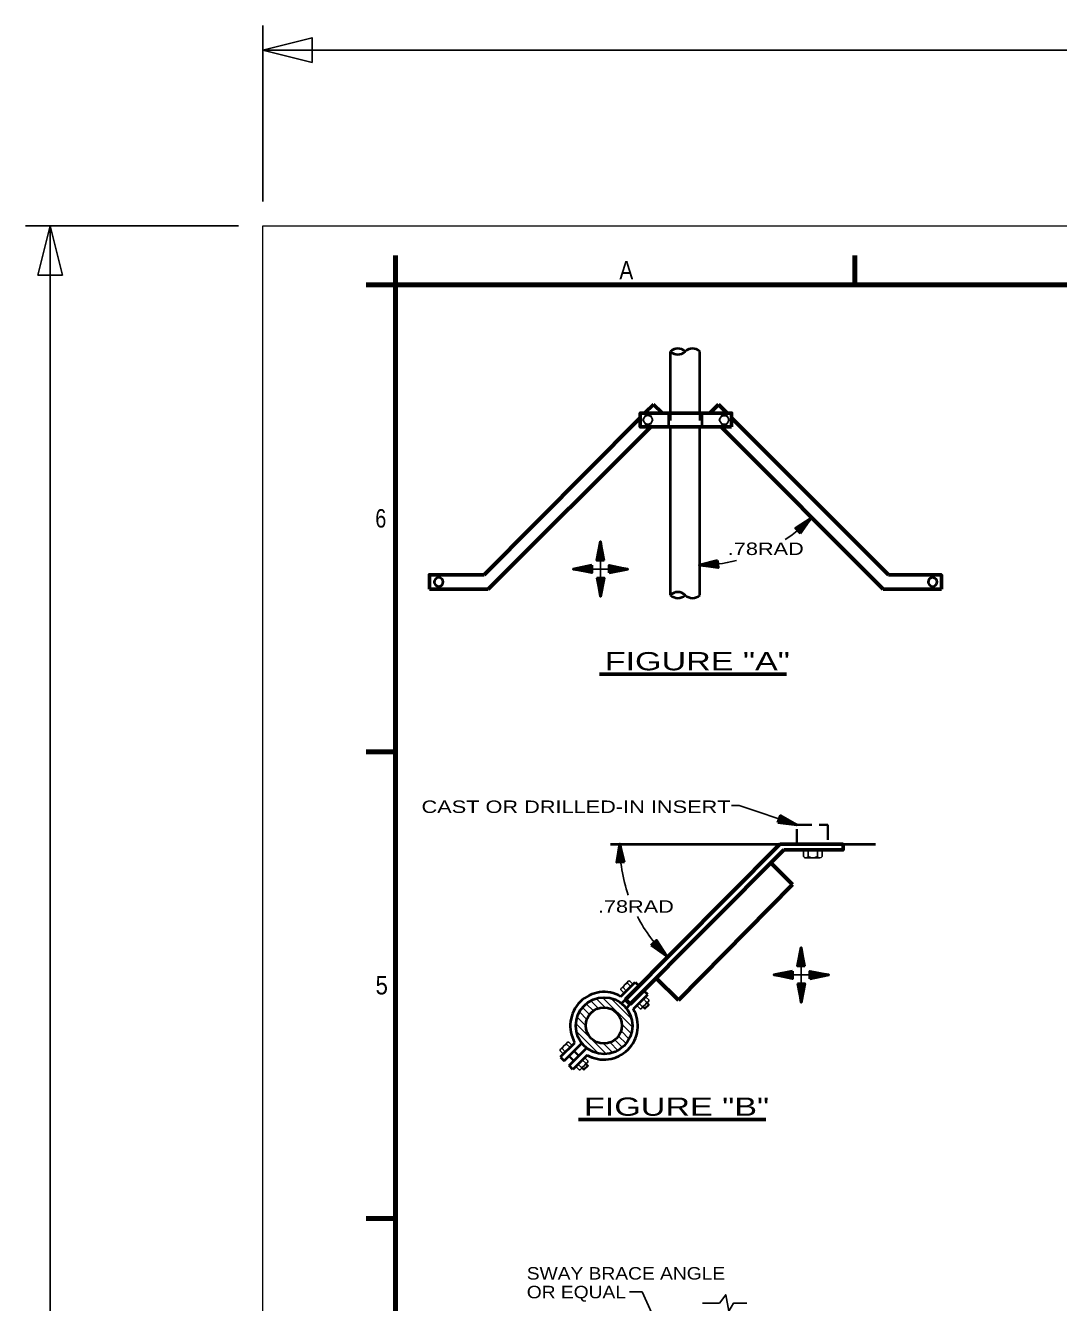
# Model space of a CAD drawing. Extents: x 55 to 190, y 198 to 264.
# Drawn here: x 57.66 to 78.68, y 235.95 to 261.93 of the extents above; entities that cross this region are included whole.
import ezdxf
from ezdxf.enums import TextEntityAlignment as Align

# ---------------------------------------------------------------- set-up
doc = ezdxf.new("R2010")
doc.units = 0
doc.header["$LTSCALE"] = 0.1
doc.linetypes.add('MEDIUM_DASHED', pattern=[4.5, 3, -1.5])
doc.linetypes.add('SHORT_DASHED', pattern=[2.7, 1.5, -1.2])
for name, color, linetype, lineweight in [('1', 7, 'Continuous', 25), ('2', 7, 'Continuous', 40), ('3', 7, 'Continuous', 25)]:
    doc.layers.add(name, color=color, linetype=linetype, lineweight=lineweight)

msp = doc.modelspace()

# ---------------------------------------------------------------- linework, layer by layer
at = {"layer": '1', "lineweight": 80}
for p, q in [((74.5415, 257.2525), (74.5415, 256.6525)), ((65.1915, 247.1525), (64.5915, 247.1525)), ((65.1915, 237.6525), (64.5915, 237.6525))]:
    msp.add_line(p, q, dxfattribs=at)
at = {"layer": '1', "lineweight": 13}
msp.add_lwpolyline([(62.4915, 257.8525), (146.5927, 257.8525), (146.5927, 198.4512), (62.4915, 198.4512)], close=True, dxfattribs=at)
at = {"layer": '1', "lineweight": 80}
msp.add_lwpolyline([(65.1915, 257.2525), (65.1915, 256.6525), (64.5915, 256.6525)], dxfattribs=at)
msp.add_lwpolyline([(65.1915, 256.6525), (145.3927, 256.6525), (145.3927, 199.6512), (65.1915, 199.6512)], close=True, dxfattribs=at)
at = {"layer": '2'}
for p, q in [((70.7891, 254.0452), (70.7891, 255.2974)), ((71.3844, 254.0452), (71.3844, 255.2974)), ((70.7476, 254.0459), (70.7476, 253.7642)), ((71.4265, 254.0483), (71.4265, 253.7626)), ((70.7891, 250.3421), (70.7891, 253.7644)), ((71.3844, 250.3421), (71.3844, 253.7644)), ((73.6593, 251.9108), (73.3442, 251.6869)), ((73.6593, 251.9108), (73.3701, 251.66)), ((73.3831, 251.6459), (73.6593, 251.9108)), ((73.6593, 251.9108), (73.3958, 251.6332)), ((73.6593, 251.9108), (73.4069, 251.6205)), ((73.6593, 251.9108), (73.4222, 251.6054)), ((69.3611, 251.4303), (69.305, 251.048)), ((69.3611, 251.4303), (69.3424, 251.048)), ((69.3617, 251.0477), (69.3611, 251.4303)), ((69.3611, 251.4303), (69.3966, 251.0474)), ((69.3611, 251.4303), (69.3794, 251.048)), ((69.3611, 251.4303), (69.418, 251.048)), ((71.3683, 250.9514), (71.7472, 251.0281)), ((68.8026, 250.8715), (69.1849, 250.9284)), ((68.8026, 250.8715), (69.1855, 250.9069)), ((68.8026, 250.8715), (69.1849, 250.8897)), ((69.1852, 250.872), (68.8026, 250.8715)), ((68.8026, 250.8715), (69.1849, 250.8154)), ((68.8026, 250.8715), (69.1849, 250.8527)), ((69.9199, 250.8715), (69.5371, 250.836)), ((69.5374, 250.871), (69.9199, 250.8715)), ((69.9199, 250.8715), (69.5376, 250.9276)), ((69.9199, 250.8715), (69.5376, 250.8903)), ((69.9199, 250.8715), (69.5376, 250.8532)), ((69.9199, 250.8715), (69.5376, 250.8146)), ((71.3683, 250.9514), (71.7487, 251.007)), ((71.3683, 250.9514), (71.7493, 250.99)), ((71.7503, 250.972), (71.3683, 250.9514)), ((71.3683, 250.9514), (71.7511, 250.953)), ((71.3683, 250.9514), (71.753, 250.9157)), ((69.3611, 250.313), (69.3043, 250.6953)), ((69.3611, 250.313), (69.3257, 250.6958)), ((69.3611, 250.313), (69.3429, 250.6953)), ((69.3606, 250.6955), (69.3611, 250.313)), ((69.3611, 250.313), (69.4172, 250.6953)), ((69.3611, 250.313), (69.3799, 250.6953)), ((73.3608, 245.6642), (73.0161, 245.8389)), ((73.3608, 245.6642), (72.9804, 245.732)), ((73.3608, 245.6642), (72.9865, 245.7526)), ((73.3608, 245.6642), (72.9925, 245.7685)), ((72.9978, 245.7854), (73.3608, 245.6642)), ((73.3608, 245.6642), (73.0042, 245.8036)), ((69.5635, 245.2753), (74.9581, 245.2753)), ((69.7532, 245.2822), (69.7175, 244.8975)), ((69.7739, 244.9001), (69.7532, 245.2822)), ((69.7532, 245.2822), (69.8088, 244.9017)), ((69.7532, 245.2822), (69.7548, 244.8993)), ((69.7532, 245.2822), (69.7919, 244.9012)), ((69.7532, 245.2822), (69.83, 244.9033)), ((70.7126, 242.9911), (70.4073, 243.2282)), ((70.7126, 242.9911), (70.4224, 243.2436)), ((70.7126, 242.9911), (70.4351, 243.2547)), ((70.4478, 243.2674), (70.7126, 242.9911)), ((70.7126, 242.9911), (70.4618, 243.2803)), ((70.7126, 242.9911), (70.4888, 243.3063)), ((73.4474, 243.1705), (73.3913, 242.7882)), ((73.4474, 243.1705), (73.4286, 242.7882)), ((73.4479, 242.7879), (73.4474, 243.1705)), ((73.4474, 243.1705), (73.4828, 242.7877)), ((73.4474, 243.1705), (73.4656, 242.7882)), ((73.4474, 243.1705), (73.5042, 242.7882)), ((69.7787, 242.1733), (70.0705, 242.4651)), ((70.0705, 242.4651), (70.1464, 242.3892)), ((72.8888, 242.6117), (73.2712, 242.6686)), ((72.8888, 242.6117), (73.2717, 242.6472)), ((72.8888, 242.6117), (73.2712, 242.63)), ((73.2714, 242.6123), (72.8888, 242.6117)), ((72.8888, 242.6117), (73.2712, 242.5556)), ((72.8888, 242.6117), (73.2712, 242.5929)), ((73.4474, 242.0532), (73.3905, 242.4355)), ((73.4474, 242.0532), (73.4119, 242.436)), ((73.4474, 242.0532), (73.4291, 242.4355)), ((73.4468, 242.4358), (73.4474, 242.0532)), ((73.4474, 242.0532), (73.5035, 242.4355)), ((73.4474, 242.0532), (73.4662, 242.4355)), ((74.0062, 242.6117), (73.6233, 242.5763)), ((73.6236, 242.6112), (74.0062, 242.6117)), ((74.0062, 242.6117), (73.6238, 242.6678)), ((74.0062, 242.6117), (73.6238, 242.6305)), ((74.0062, 242.6117), (73.6238, 242.5935)), ((74.0062, 242.6117), (73.6238, 242.5548)), ((70.0305, 241.9214), (70.3224, 242.2133)), ((70.3224, 242.2133), (70.2446, 242.2913)), ((69.7914, 242.0325), (69.8705, 242.1122)), ((69.889, 241.9355), (69.9686, 242.0156)), ((68.5494, 240.943), (68.8394, 241.233)), ((68.6248, 240.8639), (68.9809, 241.22)), ((68.547, 240.9417), (68.6248, 240.8639)), ((68.7211, 240.7678), (69.0772, 241.1237)), ((69.0907, 240.9819), (68.7989, 240.6901)), ((68.7989, 240.6901), (68.7211, 240.7678))]:
    msp.add_line(p, q, dxfattribs=at)
at = {"layer": '2', "lineweight": 60}
for p, q in [((70.442, 254.2227), (70.2665, 254.0473)), ((70.442, 254.2227), (70.6176, 254.0473)), ((71.5974, 254.0483), (71.7657, 254.2166)), ((71.9337, 254.0483), (71.7657, 254.2166)), ((66.9965, 250.7559), (70.1694, 253.9512)), ((70.2658, 254.0462), (70.2665, 254.0473)), ((71.9355, 254.0465), (71.9347, 254.0473)), ((75.2264, 250.7527), (72.0311, 253.9512)), ((70.3867, 253.7631), (67.0775, 250.4593)), ((75.1158, 250.4593), (71.8154, 253.7626)), ((67.0775, 250.4593), (65.879, 250.4593)), ((75.1158, 250.4593), (76.2996, 250.4593)), ((69.3389, 248.7339), (73.1471, 248.7339)), ((69.8705, 242.1122), (73.0153, 245.2716)), ((69.9686, 242.0156), (73.0949, 245.1568)), ((73.0153, 245.2716), (74.2988, 245.2753)), ((73.2717, 244.4495), (72.8293, 244.8898)), ((70.9478, 242.0992), (73.2717, 244.4495)), ((70.9478, 242.0992), (70.4978, 242.5472)), ((69.8705, 242.1122), (69.9686, 242.0156)), ((68.9164, 239.6693), (72.7245, 239.6693))]:
    msp.add_line(p, q, dxfattribs=at)
at = {"layer": '2', "linetype": 'SHORT_DASHED', "lineweight": 35}
for p, q in [((70.7891, 254.0452), (70.7891, 253.7626)), ((71.3844, 254.0452), (71.3844, 253.7626))]:
    msp.add_line(p, q, dxfattribs=at)
at = {"layer": '2', "lineweight": 25}
for p, q in [((69.3611, 250.313), (69.3611, 251.4303)), ((68.8026, 250.8715), (69.9199, 250.8715)), ((73.8723, 245.1565), (73.4931, 245.1565)), ((73.4934, 245.0242), (73.4931, 245.1565)), ((73.5876, 245.0242), (73.5876, 245.1568)), ((73.7786, 245.0245), (73.7786, 245.1565)), ((73.8718, 245.0242), (73.8723, 245.1565)), ((73.8247, 244.9959), (73.5408, 244.9959)), ((73.4474, 242.0532), (73.4474, 243.1705)), ((69.7871, 242.3453), (69.921, 242.4792)), ((69.912, 242.4437), (69.9744, 242.3813)), ((69.9564, 242.4882), (70.0189, 242.426)), ((72.8888, 242.6117), (74.0062, 242.6117)), ((69.7781, 242.3098), (69.8403, 242.2474)), ((69.8223, 242.3538), (69.8845, 242.2916)), ((69.8403, 242.2474), (70.0189, 242.426)), ((70.1054, 241.986), (70.2814, 242.1672)), ((70.1689, 241.9249), (70.1054, 241.986)), ((70.212, 241.9696), (70.1491, 242.031)), ((70.2041, 241.9344), (70.3361, 242.0701)), ((70.3007, 242.0606), (70.2374, 242.1223)), ((70.3446, 242.1058), (70.2814, 242.1672)), ((68.5478, 241.1031), (68.6817, 241.237)), ((68.601, 241.0052), (68.7796, 241.1838)), ((68.6727, 241.2015), (68.7351, 241.139)), ((68.7171, 241.246), (68.7796, 241.1838)), ((68.5388, 241.0676), (68.601, 241.0052)), ((68.583, 241.1115), (68.6452, 241.0494)), ((68.8661, 240.7438), (69.0421, 240.925)), ((69.0614, 240.8184), (68.9981, 240.88)), ((69.1053, 240.8636), (69.0421, 240.925)), ((68.9296, 240.6827), (68.8661, 240.7438)), ((68.9727, 240.7274), (68.9098, 240.7887)), ((68.9648, 240.6922), (69.0968, 240.8279))]:
    msp.add_line(p, q, dxfattribs=at)
at = {"layer": '2', "lineweight": 13}
for p, q in [((69.1392, 241.8061), (68.995, 241.9503)), ((69.2175, 241.8812), (69.0725, 242.0262)), ((69.3196, 241.932), (69.1646, 242.0871)), ((69.4572, 241.9479), (69.2733, 242.1315)), ((70.0123, 241.5463), (69.4045, 242.154)), ((69.9964, 241.7156), (69.5731, 242.1384)), ((69.0627, 241.5759), (68.8859, 241.7529)), ((69.0847, 241.7074), (68.9322, 241.8598)), ((69.4828, 241.0025), (68.8608, 241.6246)), ((69.3199, 241.0123), (68.8706, 241.4616)), ((69.9453, 241.3065), (69.7805, 241.4711)), ((69.9898, 241.4147), (69.7964, 241.6087)), ((69.6112, 241.0277), (69.4246, 241.2142)), ((69.7181, 241.074), (69.5556, 241.2362)), ((69.8085, 241.1367), (69.6546, 241.2907)), ((69.8842, 241.2142), (69.7297, 241.369))]:
    msp.add_line(p, q, dxfattribs=at)
at = {"layer": '2', "lineweight": 35}
for p, q in [((68.7214, 240.9605), (68.8177, 240.8644)), ((68.823, 241.0621), (68.9193, 240.966))]:
    msp.add_line(p, q, dxfattribs=at)
at = {"layer": '2', "lineweight": 60}
msp.add_lwpolyline([(72.0292, 253.7629), (70.1705, 253.7629), (70.1705, 254.0459), (72.0292, 254.0459)], close=True, dxfattribs=at)
at = {"layer": '2', "lineweight": 25}
for points in [[(70.4293, 253.9081), (70.3779, 253.819), (70.2755, 253.819), (70.2247, 253.9081), (70.2755, 253.9957), (70.3779, 253.9957)], [(71.9821, 253.9055), (71.9308, 253.8163), (71.8284, 253.8163), (71.7776, 253.9055), (71.8284, 253.993), (71.9308, 253.993)]]:
    msp.add_lwpolyline(points, close=True, dxfattribs=at)
for points in [[(70.4144, 253.9081), (70.4144, 253.902), (70.4134, 253.8965), (70.4126, 253.8909), (70.4118, 253.8854), (70.4099, 253.8801), (70.4084, 253.8748), (70.4062, 253.8703), (70.4033, 253.8645), (70.4007, 253.86), (70.3978, 253.8557), (70.3943, 253.8512), (70.3906, 253.8473), (70.3864, 253.8436), (70.3827, 253.8396), (70.3779, 253.8361), (70.3737, 253.833), (70.3692, 253.8306), (70.3639, 253.8279), (70.3591, 253.8253), (70.3536, 253.8242), (70.3486, 253.8219), (70.343, 253.8213), (70.3377, 253.8205), (70.3319, 253.82), (70.3271, 253.82), (70.3213, 253.82), (70.3155, 253.8205), (70.3099, 253.8213), (70.3046, 253.8219), (70.2996, 253.8242), (70.2938, 253.8253), (70.2893, 253.8279), (70.2843, 253.8306), (70.2792, 253.833), (70.2753, 253.8361), (70.2705, 253.8396), (70.2668, 253.8436), (70.2628, 253.8473), (70.2586, 253.8512), (70.2552, 253.8557), (70.2528, 253.86), (70.2499, 253.8645), (70.247, 253.8703), (70.2448, 253.8748), (70.2433, 253.8801), (70.2414, 253.8854), (70.2406, 253.8909), (70.2401, 253.8965), (70.239, 253.902), (70.239, 253.9081), (70.239, 253.9129), (70.2401, 253.9182), (70.2406, 253.9237), (70.2414, 253.9295), (70.2433, 253.9346), (70.2448, 253.9399), (70.247, 253.9443), (70.2499, 253.9497), (70.2528, 253.9547), (70.2552, 253.9589), (70.2586, 253.9637), (70.2628, 253.9674), (70.2668, 253.9713), (70.2705, 253.9751), (70.2753, 253.9785), (70.2792, 253.9817), (70.2843, 253.9843), (70.2893, 253.9867), (70.2938, 253.9893), (70.2996, 253.9907), (70.3046, 253.9923), (70.3099, 253.9936), (70.3155, 253.9944), (70.3213, 253.9949), (70.3271, 253.9949), (70.3319, 253.9949), (70.3377, 253.9944), (70.343, 253.9936), (70.3486, 253.9923), (70.3536, 253.9907), (70.3591, 253.9893), (70.3639, 253.9867), (70.3692, 253.9843), (70.3737, 253.9817), (70.3779, 253.9785), (70.3827, 253.9751), (70.3864, 253.9713), (70.3906, 253.9674), (70.3943, 253.9637), (70.3978, 253.9589), (70.4007, 253.9547), (70.4033, 253.9497), (70.4062, 253.9443), (70.4084, 253.9399), (70.4099, 253.9346), (70.4118, 253.9295), (70.4126, 253.9237), (70.4134, 253.9182)], [(71.9673, 253.9055), (71.9673, 253.8994), (71.9662, 253.8938), (71.9654, 253.8883), (71.9646, 253.8827), (71.9628, 253.8774), (71.9612, 253.8721), (71.9591, 253.8676), (71.9562, 253.8618), (71.9535, 253.8573), (71.9506, 253.8531), (71.9472, 253.8486), (71.9435, 253.8446), (71.9392, 253.8409), (71.9355, 253.8369), (71.9308, 253.8335), (71.9265, 253.8303), (71.922, 253.8279), (71.9168, 253.8253), (71.912, 253.8227), (71.9064, 253.8216), (71.9014, 253.8192), (71.8958, 253.8187), (71.8906, 253.8179), (71.8847, 253.8174), (71.88, 253.8174), (71.8742, 253.8174), (71.8683, 253.8179), (71.8628, 253.8187), (71.8575, 253.8192), (71.8525, 253.8216), (71.8466, 253.8227), (71.8421, 253.8253), (71.8371, 253.8279), (71.8321, 253.8303), (71.8281, 253.8335), (71.8234, 253.8369), (71.8196, 253.8409), (71.8157, 253.8446), (71.8114, 253.8486), (71.808, 253.8531), (71.8056, 253.8573), (71.8027, 253.8618), (71.7998, 253.8676), (71.7977, 253.8721), (71.7961, 253.8774), (71.7942, 253.8827), (71.7935, 253.8883), (71.7929, 253.8938), (71.7919, 253.8994), (71.7919, 253.9055), (71.7919, 253.9102), (71.7929, 253.9155), (71.7935, 253.9211), (71.7942, 253.9269), (71.7961, 253.9319), (71.7977, 253.9372), (71.7998, 253.9417), (71.8027, 253.947), (71.8056, 253.952), (71.808, 253.9563), (71.8114, 253.961), (71.8157, 253.9647), (71.8196, 253.9687), (71.8234, 253.9724), (71.8281, 253.9758), (71.8321, 253.979), (71.8371, 253.9817), (71.8421, 253.9841), (71.8466, 253.9867), (71.8525, 253.988), (71.8575, 253.9896), (71.8628, 253.9909), (71.8683, 253.9917), (71.8742, 253.9923), (71.88, 253.9923), (71.8847, 253.9923), (71.8906, 253.9917), (71.8958, 253.9909), (71.9014, 253.9896), (71.9064, 253.988), (71.912, 253.9867), (71.9168, 253.9841), (71.922, 253.9817), (71.9265, 253.979), (71.9308, 253.9758), (71.9355, 253.9724), (71.9392, 253.9687), (71.9435, 253.9647), (71.9472, 253.961), (71.9506, 253.9563), (71.9535, 253.952), (71.9562, 253.947), (71.9591, 253.9417), (71.9612, 253.9372), (71.9628, 253.9319), (71.9646, 253.9269), (71.9654, 253.9211), (71.9662, 253.9155)], [(72.0266, 246.0579), (72.1877, 246.0579), (73.3608, 245.6642)], [(69.952, 236.1636), (70.2089, 236.1636), (70.8507, 234.7515)], [(71.4389, 235.9305), (71.7813, 235.9305), (71.9128, 236.1025), (71.9765, 235.768), (72.0657, 235.9323), (72.3403, 235.9323)]]:
    msp.add_lwpolyline(points, dxfattribs=at)
at = {"layer": '2'}
for points in [[(73.4357, 251.5914), (73.3301, 251.7023), (73.6593, 251.9108)], [(73.4357, 251.5914), (73.6593, 251.9108), (73.3569, 251.6734)], [(69.4373, 251.048), (69.2844, 251.0482), (69.3611, 251.4303)], [(69.4373, 251.048), (69.3611, 251.4303), (69.3236, 251.0477)], [(71.7461, 251.0477), (71.754, 250.8948), (71.3683, 250.9514)], [(71.7461, 251.0477), (71.3683, 250.9514), (71.7524, 250.9339)], [(69.1849, 250.9477), (69.1847, 250.7948), (68.8026, 250.8715)], [(69.1849, 250.9477), (68.8026, 250.8715), (69.1852, 250.8339)], [(69.5376, 250.7953), (69.9199, 250.8715), (69.5374, 250.9091)], [(69.5376, 250.7953), (69.5379, 250.9482), (69.9199, 250.8715)], [(69.2849, 250.6953), (69.3611, 250.313), (69.3987, 250.6955)], [(69.2849, 250.6953), (69.4379, 250.695), (69.3611, 250.313)], [(72.974, 245.7137), (73.023, 245.8587), (73.3608, 245.6642)], [(72.974, 245.7137), (73.3608, 245.6642), (73.01, 245.8216)], [(69.8496, 244.9043), (69.6966, 244.8964), (69.7532, 245.2822)], [(69.8496, 244.9043), (69.7532, 245.2822), (69.7358, 244.898)], [(70.3933, 243.2147), (70.5041, 243.3203), (70.7126, 242.9911)], [(70.3933, 243.2147), (70.7126, 242.9911), (70.4753, 243.2936)], [(73.5236, 242.7882), (73.3706, 242.7885), (73.4474, 243.1705)], [(73.5236, 242.7882), (73.4474, 243.1705), (73.4098, 242.7879)], [(73.2712, 242.6879), (73.2709, 242.535), (72.8888, 242.6117)], [(73.2712, 242.6879), (72.8888, 242.6117), (73.2714, 242.5742)], [(73.3712, 242.4355), (73.4474, 242.0532), (73.4849, 242.4358)], [(73.3712, 242.4355), (73.5241, 242.4353), (73.4474, 242.0532)], [(73.6238, 242.5355), (74.0062, 242.6117), (73.6236, 242.6493)], [(73.6238, 242.5355), (73.6241, 242.6885), (74.0062, 242.6117)]]:
    msp.add_lwpolyline(points, dxfattribs=at)
at = {"layer": '2', "lineweight": 60}
for points in [[(66.9965, 250.7559), (65.879, 250.7559), (65.879, 250.4593)], [(75.2264, 250.7527), (76.2993, 250.7527), (76.2993, 250.4593)], [(74.2988, 245.2753), (74.2988, 245.1568), (73.0949, 245.1568)]]:
    msp.add_lwpolyline(points, dxfattribs=at)
at = {"layer": '2'}
for points in [[(66.0681, 250.699), (66.0401, 250.694), (66.0147, 250.6807), (65.9948, 250.6604), (65.9821, 250.635), (65.9782, 250.6066), (65.9829, 250.5786), (65.9962, 250.5535), (66.0165, 250.5336), (66.0419, 250.5209), (66.0703, 250.5167), (66.0983, 250.5214), (66.1234, 250.5347), (66.1435, 250.5551), (66.156, 250.5807), (66.1602, 250.609), (66.1554, 250.6371), (66.1422, 250.6622), (66.1218, 250.6821), (66.0962, 250.6948)], [(76.1202, 250.699), (76.0921, 250.694), (76.067, 250.6807), (76.0469, 250.6604), (76.0345, 250.635), (76.0302, 250.6066), (76.035, 250.5786), (76.0482, 250.5535), (76.0686, 250.5336), (76.0943, 250.5209), (76.1223, 250.5167), (76.1503, 250.5214), (76.1757, 250.5347), (76.1956, 250.5551), (76.2083, 250.5807), (76.2123, 250.609), (76.2075, 250.6371), (76.1943, 250.6622), (76.1739, 250.6821), (76.1485, 250.6948)]]:
    msp.add_lwpolyline(points, close=True, dxfattribs=at)
at = {"layer": '2', "linetype": 'MEDIUM_DASHED', "lineweight": 35}
msp.add_lwpolyline([(73.3608, 245.2779), (73.3608, 245.6642), (73.9903, 245.6642), (73.9903, 245.2753)], dxfattribs=at)
at = {"layer": '2', "lineweight": 35}
for points in [[(70.23, 241.9622), (70.2652, 241.9273), (70.3438, 242.0061), (70.3089, 242.041)], [(68.9907, 240.7202), (69.0259, 240.6853), (69.1045, 240.7641), (69.0696, 240.7991)]]:
    msp.add_lwpolyline(points, dxfattribs=at)
at = {"layer": '2'}
for centre, radius in [((69.436, 241.5777), 0.5772), ((69.4299, 241.5814), 0.3674)]:
    msp.add_circle(centre, radius, dxfattribs=at)
for centre, radius, start, end in [((70.9379, 255.1434), 0.2142, 45.9775, 134.02119), ((70.9379, 255.4514), 0.2142, 225.97881, 314.0225), ((71.2356, 255.1434), 0.2142, 45.97881, 134.0225), ((70.9379, 250.1881), 0.2142, 45.9775, 134.02119), ((70.9379, 250.4961), 0.2142, 225.97881, 314.0225), ((71.2356, 250.4961), 0.2142, 225.9775, 314.02119), ((69.4347, 241.5776), 0.6879, 60.01092, 209.9726), ((69.4347, 241.5775), 0.6879, 239.97776, 29.98899)]:
    msp.add_arc(centre, radius, start, end, dxfattribs=at)
at = {"layer": '2', "lineweight": 25}
for centre, radius, start, end in [((71.3683, 254.1666), 3.2152, 303.01479, 315.44091), ((71.3683, 254.1666), 3.2152, 270, 283.71277), ((72.9685, 245.2822), 3.2152, 180, 198.96664), ((73.5405, 245.0497), 0.0537, 208.34206, 331.66132), ((73.683, 245.1711), 0.175, 237.03159, 302.96841), ((73.8251, 245.049), 0.053, 207.91313, 332.05962), ((72.9685, 245.2822), 3.2152, 207.45917, 225.44342), ((69.9364, 242.3296), 0.1167, 102.03159, 167.96841), ((69.9463, 242.4539), 0.0358, 73.34206, 196.66132), ((69.8119, 242.3201), 0.0353, 72.91313, 197.05962), ((70.1786, 241.9587), 0.0353, 253.78561, 17.9321), ((70.1862, 242.0834), 0.1167, 282.87682, 348.81364), ((70.3104, 242.0952), 0.0358, 254.18391, 17.50317), ((68.6971, 241.0873), 0.1167, 102.03159, 167.96841), ((68.707, 241.2117), 0.0358, 73.34206, 196.66132), ((68.5726, 241.0779), 0.0353, 72.91313, 197.05962), ((68.9393, 240.7165), 0.0353, 253.78561, 17.9321), ((68.9469, 240.8412), 0.1167, 282.87682, 348.81364), ((69.0711, 240.8529), 0.0358, 254.18391, 17.50317)]:
    msp.add_arc(centre, radius, start, end, dxfattribs=at)
at = {"layer": '3'}
for p, q in [((62.4915, 258.3525), (62.4915, 261.9312)), ((62.4915, 261.4312), (146.5927, 261.4312)), ((61.9915, 257.8525), (57.6602, 257.8525)), ((58.1602, 257.8525), (58.1602, 198.4512))]:
    msp.add_line(p, q, dxfattribs=at)
for points in [[(63.4915, 261.1812), (62.4915, 261.4312), (63.4915, 261.6812)], [(57.9102, 256.8525), (58.1602, 257.8525), (58.4102, 256.8525)]]:
    msp.add_lwpolyline(points, close=True, dxfattribs=at)

# ---------------------------------------------------------------- texts
at = {"layer": '1'}
for s, width, p in [('A', 0.85, (69.8872, 256.765)), ('6', 0.8, (64.8904, 251.715)), ('5', 0.9, (64.9092, 242.215))]:
    msp.add_text(s, height=0.375, dxfattribs=dict(at, width=width)).set_placement(p, align=Align.CENTER)
at = {"layer": '2'}
for s, height, width, p in [('.78RAD', 0.254, 1.3, (72.7254, 251.1568)), ('FIGURE "A"', 0.3704, 1.4, (71.3325, 248.8109)), ('.78RAD', 0.254, 1.3, (70.0815, 243.8777)), ('FIGURE "B"', 0.3704, 1.4, (70.91, 239.7463))]:
    msp.add_text(s, height=height, dxfattribs=dict(at, width=width)).set_placement(p, align=Align.CENTER)
for s, height, width, p in [('CAST OR DRILLED-IN INSERT', 0.2543, 1.3, (65.7199, 245.9074)), ('SWAY BRACE ANGLE', 0.254, 1.15, (67.8617, 236.4123)), ('OR EQUAL', 0.254, 1.15, (67.8617, 236.0313))]:
    msp.add_text(s, height=height, dxfattribs=dict(at, width=width)).set_placement(p)

doc.saveas('drawing.dxf')
